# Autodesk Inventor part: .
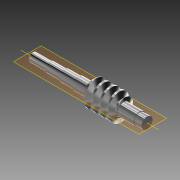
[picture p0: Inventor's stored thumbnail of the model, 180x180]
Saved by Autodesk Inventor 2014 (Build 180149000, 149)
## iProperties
FeatNameP00020918111132155: J1301BS1
ProtocolIDP00020918111132155: P00020918111132155
ProtocolP00020918111132155: P00020918111132155<@PID>[Version]<@EL>Version=2.2<@EL>[Data]<@EL>H1=45.96{mm<@EL>th=h11{nd<@EL>t2=3.3{mm<@EL>mass=0.0269098{kg<@EL>pocper=1{nd<@EL>gl=10{mm<@EL>
Shininess: 20.0
Length Units: 11269
Angle Units: 11279
Time Units: 11290
Mass Units: 11283
Length Display Precision: 3
Angle Display Precision: 2
Created: 2001-01
Part Number: .
Material: Steel, Mild
Description: Worm gearing 1/25, 165.
Document SubType Name: Modeling
Designer: Roman
Density: 7.86 g/cm^3
Appearance: Chrome - Polished
Density: 7.86
Volumn: 50.08734451905087
Area: 124.31101067698765
PropertySet Name: Model Information
Control State: 0
Master: False
Checked Out: False
Author: PaulN
ProtocolID: P00020917093204537
Protocol: P00020917093204537<@PID>[Version]<@EL>Version=2.2<@EL>[Synchronize]<@EL>ChangedVars=<@EL>[Calc]<@EL>ScnVisible=0<@EL>WizardMode=1<@EL>Optim=1<@EL>CalcName=GEAR3
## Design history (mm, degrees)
extrude "ExtrusionMidplane1" new body stored distance "d6" = 127 (= prf_b1); taper "d7" = 0 deg
  node "Sketch2" dims "d5" = 100 (= prf_da1)
chamfer "Chamfer1" distance "d8" = 8.00735 (= msp_ukos1); stored, may be unused: second distance "d9" = 22 (= 0.5 x msp_ukos2), angle "d74" = 45 deg
node "WorkAxis1"
chamfer "Chamfer2" distance "d10" = 8.00735 (= msp_ukos1); stored, may be unused: second distance "d11" = 22 (= 0.5 x msp_ukos2), angle "d75" = 45 deg
sketch "Sketch4"
  geometry: L1 (0, 55)-(0, 23.5) reference; L2 (-121.632, 50.5)-(-113.442, 28); L3 (-106.47, 28)-(-98.28, 50.5); L4 (-126.302, 0)-(-93.61, 0) reference; L5 (-121.632, 50.5)-(-109.956, 50.5); L6 (-109.956, 50.5)-(-98.28, 50.5); L7 (-113.442, 28)-(-109.956, 28); L8 (-109.956, 28)-(-106.47, 28); L9 (-109.956, 40)-(-102.102, 40); L10 (-109.956, 50.5)-(-109.956, 28)
  constraints: 16 end point, 3 equal length, 3 parallel, 2 collinear, 2 point on line
  dimensions: "d24" = 110 deg angle of L7 L2 (computed from prf_alfax); "d25" = 109.956 distance from line of L1 L5.end (= msp_dist); "d26" = 7.854 distance of L9.start L9.end (= 0.25 x prf_px); "d27" = 28 distance between parallel lines of L4 L7 (= 0.5 x prf_df1); "d28" = 40 distance between parallel lines of L4 L9 (= 0.5 x prf_d1); "d29" = 50.5 distance between parallel lines of L4 L5 (= 0.505 x prf_da1)
coil "Coil2" sketch "Sketch4" pitch "d30" = 31.416 (= prf_px); turns "d32" = 7 (= msp_n); dims "d31" = 10, "d33" = 0, angle "d34" = 90 deg, angle "d35" = 90 deg, "d36" = 0, "d37" = 0
node "WorkPlane3"
workplane "Work Plane4"
workplane "Work Plane5"
sketch "Sketch5"
  geometry: L1 (-63.5, 0)-(-130, 0); L2 (-130, 0)-(-130, 25); L3 (-130, 25)-(-63.5, 25); L4 (-63.5, 25)-(-63.5, 0); L5 (63.5, 0)-(120, 0); L6 (120, 0)-(120, 25); L7 (120, 25)-(63.5, 25); L8 (63.5, 25)-(63.5, 0); L9 (-63.5, -28)-(-63.5, 28) reference; L10 (63.5, 28)-(63.5, -28) reference; L11 (170, 0)-(-180, 0) reference; L12 (0, -39.2)-(0, 39.2) reference
  constraints: 16 end point, 4 collinear, 4 parallel, 2 horizontal, 2 perpendicular
  dimensions: "d46" = 25 distance between parallel lines of L5 L7; "d49" = 25 distance between parallel lines of L1 L3; "L_shaft_in1" = 120 distance between parallel lines of L6 L12; "L_shaft_in2" = 130 distance between parallel lines of L2 L12
revolve "Revolution1" sketch "Sketch5" stored, may be unused: angle "d50" = 90 deg
sketch "Sketch6"
  geometry: C1 r 25 at (0, 0) reference; C2 r 22.5 at (0, 0)
  constraints: 1 centre point, 1 coincident
  dimensions: "d51" = 45 diameter of C2
extrude "Extrusion2" join sketch "Sketch6" distance "d52" = 55; taper "d53" = 0 deg
sketch "Sketch7"
  geometry: C1 r 25 at (0, 0) reference; C2 r 22.5 at (0, 0)
  constraints: 1 centre point, 1 coincident
  dimensions: "d54" = 45 diameter of C2
extrude "Extrusion3" join sketch "Sketch7" distance "d55" = 30; taper "d56" = 0 deg
sketch "Sketch8"
  geometry: C1 r 22.5 at (0, 0) reference; C2 r 20 at (0, 0)
  constraints: 1 centre point, 1 coincident
  dimensions: "d57" = 40 diameter of C2
extrude "Extrusion4" join sketch "Sketch8" distance "d58" = 60; taper "d59" = 0 deg
sketch "Sketch9"
  geometry: C1 r 20 at (0, 0) reference; C2 r 17.5 at (0, 0)
  constraints: 1 centre point, 1 coincident
  dimensions: "d62" = 35 diameter of C2
extrude "Extrusion5" join sketch "Sketch9" distance "d63" = 70; taper "d64" = 0 deg
chamfer "Chamfer3" distance "d72" = 0.5; stored, may be unused: second distance "d73" = 0.5, angle "d76" = 45 deg
sketch "Sketch10"
  geometry: L1 (5, 12.5)-(-5, 12.5); L2 (-5, 12.5)-(-5, 20.5); L3 (-5, 20.5)-(5, 20.5); L4 (5, 20.5)-(5, 12.5); C1 r 17.5 at (0, 0) reference; 1 further point
  constraints: 8 end point, 2 parallel, 1 horizontal, 1 midpoint, 1 perpendicular, 1 vertical alignment
  dimensions: "key_width" = 10 distance of L2.end L3.end; "key_height" = 8 distance of L3.end L1.start; "key_t1" = 5 distance edge to line of C1 L1
extrude "Extrusion6" cut sketch "Sketch10" taper "d69" = 0 deg; distance "key_L" = 32
sketch "Sketch11"
  geometry: L1 (-5, 12.5)-(5, 12.5) reference; L2 (5, 12.5)-(5, 16.771) reference; L3 (-12.163, 42.5)-(8.557, 42.5); L4 (-5, 12.5)-(5, 12.5); L5 (5, 12.5)-(5, 42.5); L6 (5, 42.5)-(-5, 42.5); L7 (-5, 42.5)-(-5, 12.5)
  constraints: 10 end point, 3 parallel, 2 perpendicular, 1 collinear, 1 horizontal, 1 point on line
  dimensions: "d70" = 60 diameter of L1 L3
revolve "Revolution2" sketch "Sketch11" stored, may be unused: angle "d71" = 90 deg
workplane "Work Plane10"
body "Solid1"
other parameters: "prf_a" = 165 [user parameter; used in 1 equation term], "prf_b1" = 127 [user parameter; used in 3 equation terms], "prf_df1" = 56 [user parameter; used in 2 equation terms], "msp_ukos2" = 44 (= prf_da1 - prf_df1) [user parameter; used in 3 equation terms], "msp_ukos1" = 8.00735 (= 0.181985 x msp_ukos2) [user parameter; used in 2 equation terms], "prf_px" = 31.416 [user parameter; used in 4 equation terms], "msp_dist" = 109.956 (computed from prf_b1, prf_px) [user parameter; used in 1 equation term], "msp_n" = 7 (computed from prf_b1, prf_px) [user parameter; used in 1 equation term], "prf_alfax" = 20 deg [user parameter; used in 1 equation term], "d12" = 110 deg (derived), "d14" = 3.1425 (derived), "d38" = 165 (= prf_a), "d40" = 0, "d41" = 0, "d43" = 0, "d79" = 0, "d80" = 0, "d81" = 0
